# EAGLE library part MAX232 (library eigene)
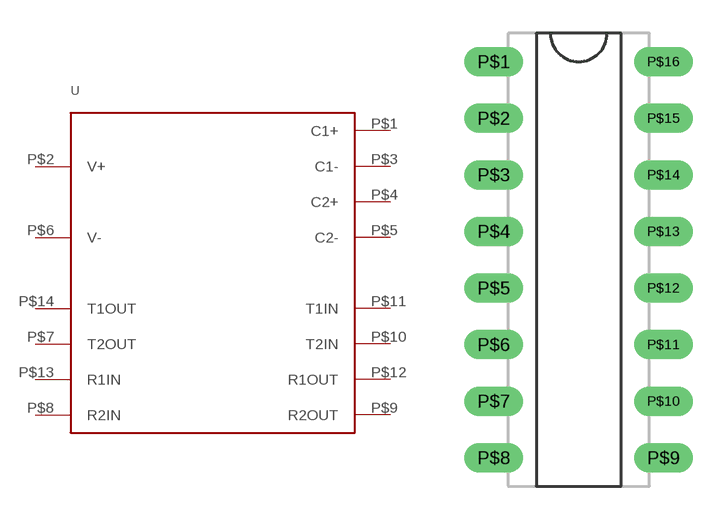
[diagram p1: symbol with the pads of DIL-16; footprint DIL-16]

Designator prefix -

## MAX232  [DIL-16]
P$1  C1+
P$2  V+
P$3  C1-
P$4  C2+
P$5  C2-
P$6  V-
P$7  T2OUT
P$8  R2IN
P$9  R2OUT
P$10  T2IN
P$11  T1IN
P$12  R1OUT
P$13  R1IN
P$14  T1OUT

## Footprint DIL-16 (pad centres in mm)
drill 0.813 long: P$1 -3.81,8.89; P$2 -3.81,6.35; P$3 -3.81,3.81; P$4 -3.81,1.27; P$5 -3.81,-1.27; P$6 -3.81,-3.81; P$7 -3.81,-6.35; P$8 -3.81,-8.89; P$9 3.81,-8.89; P$10 3.81,-6.35; P$11 3.81,-3.81; P$12 3.81,-1.27; P$13 3.81,1.27; P$14 3.81,3.81; P$15 3.81,6.35; P$16 3.81,8.89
